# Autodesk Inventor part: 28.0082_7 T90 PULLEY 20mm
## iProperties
Created: 2006-12
Document SubType Name: Modeling
Designer: Andy Moles
Part Number: 28.0082_7 T90 PULLEY 20mm
Material: Aluminum-6061
Density: 2.71 g/cm^3
Author: Andy Moles
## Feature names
1. Extrusion1
2. Extrusion3
3. Extrusion4
4. Extrusion6
5. Mirror1
6. Extrusion7
7. Chamfer1
